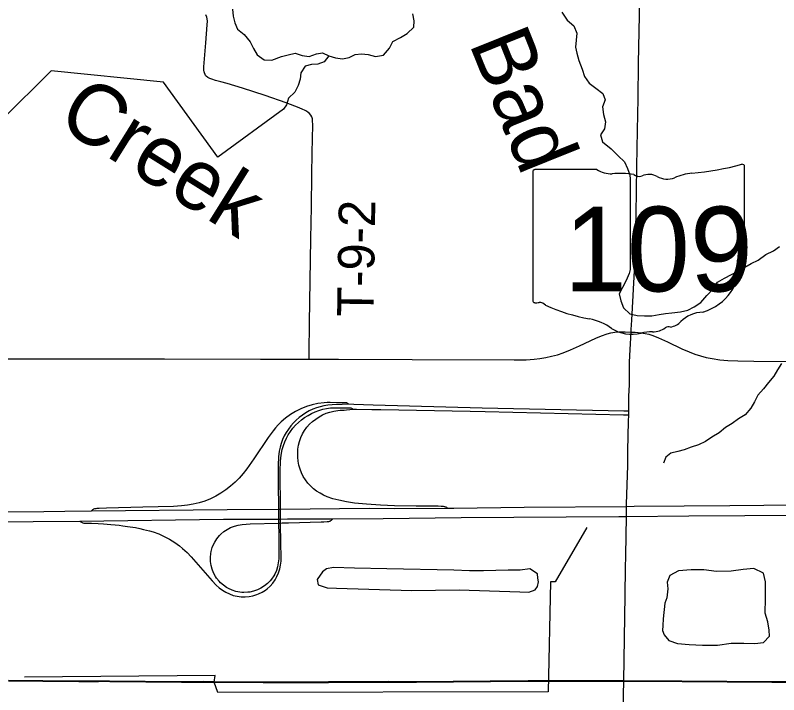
# Model space of a CAD drawing. Extents: x -21.7 to 34, y 0 to 22.
# Drawn here: x 24.718 to 25.906, y 18.47 to 19.527 of the extents above; entities that cross this region are included whole.
import ezdxf

# ---------------------------------------------------------------- set-up
doc = ezdxf.new("R2010")
doc.units = 0
for name, color, linetype in [('GM_X_County_Road', 7, 'Continuous'), ('GM_X_Interchange_Ramps', 7, 'Continuous'), ('GM_X_Interstate_Route', 7, 'Continuous'), ('GM_X_Minor_Lake', 7, 'Continuous'), ('GM_X_Minor_River', 7, 'Continuous'), ('GM_X_Minor_River_Text', 7, 'Continuous'), ('GM_X_State_Location', 7, 'Continuous'), ('GM_X_State_Route', 7, 'Continuous'), ('GM_X_State_Shield', 7, 'Continuous'), ('GM_X_Township_Road', 7, 'Continuous'), ('GM_X_Township_Road_Text', 7, 'Continuous')]:
    doc.layers.add(name, color=color, linetype=linetype)

msp = doc.modelspace()

# ---------------------------------------------------------------- linework, layer by layer
at = {"layer": 'GM_X_County_Road'}
for points in [[(24.6684, 18.492), (24.7078, 18.4915), (24.7607, 18.491), (24.8167, 18.4905), (24.8475, 18.4904), (24.8561, 18.4908), (24.8648, 18.4904), (24.9765, 18.4895), (25.0106, 18.4897), (25.0261, 18.4894), (25.1038, 18.489), (25.1753, 18.4892), (25.2057, 18.4892), (25.2989, 18.4897), (25.3424, 18.4896), (25.4575, 18.4905), (25.5165, 18.4908), (25.5538, 18.4912), (25.6651, 18.4908)], [(25.6651, 18.4908), (25.7559, 18.4905), (25.8958, 18.4896), (25.9642, 18.4893), (25.9912, 18.4891)]]:
    msp.add_lwpolyline(points, dxfattribs=at)
at = {"layer": 'GM_X_Interchange_Ramps'}
for points in [[(25.2372, 18.922), (25.2363, 18.9228), (25.2355, 18.9233), (25.2345, 18.9238), (25.2338, 18.924), (25.2327, 18.9241), (25.2318, 18.9241), (25.2297, 18.924), (25.2267, 18.9242), (25.2082, 18.9246), (25.2035, 18.9247), (25.1985, 18.9243), (25.189, 18.9232), (25.1801, 18.9212), (25.1713, 18.9183), (25.1626, 18.9147), (25.1543, 18.9106), (25.1463, 18.9061), (25.1387, 18.9005), (25.132, 18.8948), (25.1272, 18.8901), (25.1228, 18.8852), (25.1192, 18.8804), (25.1118, 18.8703), (25.0893, 18.8368), (25.0785, 18.8216), (25.0727, 18.8143), (25.0666, 18.8072), (25.0601, 18.8006), (25.0531, 18.7944), (25.0458, 18.7887), (25.038, 18.7835), (25.03, 18.7788), (25.0216, 18.7747), (25.0129, 18.7713), (25.004, 18.7685), (24.995, 18.7664), (24.9858, 18.7649), (24.9765, 18.7638), (24.9641, 18.763), (24.9166, 18.762), (24.86, 18.7601), (24.8483, 18.7598), (24.8466, 18.7598), (24.8449, 18.7596), (24.8431, 18.7594), (24.8413, 18.759), (24.8397, 18.7585), (24.8389, 18.7581), (24.838, 18.7575), (24.8371, 18.7568), (24.8364, 18.7559)], [(24.8182, 18.7401), (24.8188, 18.7395), (24.8197, 18.7388), (24.8207, 18.7383), (24.8228, 18.7376), (24.8243, 18.7371), (24.8257, 18.7369), (24.8366, 18.7367), (24.8466, 18.7363), (24.8552, 18.7358), (24.8665, 18.7348), (24.8735, 18.7343), (24.8797, 18.7337), (24.8852, 18.733), (24.8925, 18.732), (24.9051, 18.73), (24.9116, 18.7288), (24.9176, 18.7273), (24.9266, 18.7252), (24.9326, 18.7235), (24.9413, 18.7203), (24.9498, 18.7164), (24.958, 18.712), (24.966, 18.7071), (24.9735, 18.7016), (24.9783, 18.6977), (24.9852, 18.6914), (24.9916, 18.6847), (25.0243, 18.6472), (25.0307, 18.6405), (25.0354, 18.6363), (25.0403, 18.6326), (25.0456, 18.6293), (25.0512, 18.6267), (25.0571, 18.6246), (25.0631, 18.6232), (25.0693, 18.6224), (25.0755, 18.6223), (25.0817, 18.6228), (25.0878, 18.6239), (25.0938, 18.6257), (25.0967, 18.6268), (25.1022, 18.6295), (25.1075, 18.6328), (25.1099, 18.6347), (25.1145, 18.6389), (25.1186, 18.6436), (25.1222, 18.6487), (25.1252, 18.6541), (25.1277, 18.6598), (25.1297, 18.6657), (25.131, 18.6717), (25.1316, 18.6779), (25.1319, 18.6841), (25.1311, 18.7059), (25.1309, 18.7371), (25.1309, 18.7434), (25.1308, 18.7588), (25.1304, 18.8177), (25.1307, 18.8332), (25.1316, 18.8425), (25.1334, 18.8516), (25.1352, 18.8576), (25.1373, 18.8634), (25.14, 18.869), (25.1429, 18.8745), (25.1463, 18.8797), (25.15, 18.8846), (25.1542, 18.8893), (25.1586, 18.8936), (25.1633, 18.8976), (25.1683, 18.9013), (25.1736, 18.9047), (25.179, 18.9077), (25.1846, 18.9103), (25.1905, 18.9124), (25.1964, 18.9142), (25.2025, 18.9154), (25.2087, 18.9163), (25.2133, 18.9165), (25.2182, 18.9166), (25.2284, 18.9166), (25.2368, 18.9164), (25.2387, 18.9164), (25.2403, 18.9162), (25.2414, 18.9159), (25.2425, 18.9155), (25.2431, 18.915), (25.2437, 18.9142)], [(25.6731, 18.9114), (25.6655, 18.9113), (25.4446, 18.916), (25.2749, 18.9208), (25.2449, 18.9218), (25.2372, 18.922), (25.2265, 18.9216), (25.2177, 18.9214), (25.211, 18.9211), (25.2046, 18.9206), (25.1982, 18.9196), (25.1924, 18.9182), (25.1868, 18.9166), (25.181, 18.9143), (25.1754, 18.9117), (25.17, 18.9086), (25.1649, 18.9052), (25.1599, 18.9014), (25.1553, 18.8973), (25.1509, 18.8929), (25.1468, 18.8882), (25.143, 18.8833), (25.1397, 18.878), (25.1367, 18.8726), (25.1341, 18.8669), (25.132, 18.8611), (25.1302, 18.8552), (25.1289, 18.8491), (25.1276, 18.8399), (25.127, 18.8275), (25.1269, 18.7995), (25.1275, 18.7588), (25.1277, 18.7434), (25.1278, 18.737), (25.128, 18.7188), (25.1283, 18.6908), (25.128, 18.6815), (25.1273, 18.6753), (25.1261, 18.6692), (25.1243, 18.6633), (25.1218, 18.6576), (25.1203, 18.6549), (25.1168, 18.6498), (25.1148, 18.6474), (25.1104, 18.643), (25.1056, 18.6392), (25.1003, 18.6359), (25.0947, 18.6331), (25.0888, 18.6311), (25.0828, 18.6297), (25.0797, 18.6293), (25.0735, 18.629), (25.0704, 18.6292), (25.0643, 18.63), (25.0612, 18.6307), (25.0553, 18.6326), (25.0496, 18.6352), (25.0469, 18.6367), (25.0418, 18.6402), (25.0371, 18.6443), (25.035, 18.6465), (25.0311, 18.6514), (25.0294, 18.654), (25.0266, 18.6595), (25.0244, 18.6653), (25.0228, 18.6713), (25.0219, 18.6775), (25.0217, 18.6837), (25.0223, 18.6899), (25.0228, 18.6929), (25.0245, 18.6989), (25.0256, 18.7018), (25.0283, 18.7074), (25.0317, 18.7126), (25.0356, 18.7175), (25.0378, 18.7197), (25.0425, 18.7238), (25.045, 18.7256), (25.0503, 18.7288), (25.0531, 18.7301), (25.0589, 18.7322), (25.0649, 18.7338), (25.071, 18.7348), (25.0834, 18.7359), (25.1277, 18.737)], [(25.3908, 18.7602), (25.3896, 18.7611), (25.3886, 18.7616), (25.3877, 18.762), (25.3868, 18.7623), (25.3859, 18.7625), (25.3846, 18.7627), (25.3829, 18.763), (25.3807, 18.7631), (25.3763, 18.7632), (25.3651, 18.7635), (25.3418, 18.7635), (25.3082, 18.7639), (25.2864, 18.7648), (25.2646, 18.7664), (25.246, 18.7683), (25.2336, 18.7701), (25.2214, 18.7726), (25.2124, 18.775), (25.2035, 18.7781), (25.1978, 18.7806), (25.1923, 18.7836), (25.187, 18.7869), (25.1821, 18.7906), (25.1775, 18.7948), (25.1733, 18.7994), (25.1695, 18.8044), (25.1662, 18.8097), (25.1634, 18.8153), (25.1612, 18.8211), (25.1594, 18.8271), (25.1583, 18.8332), (25.1576, 18.8395), (25.1575, 18.8457), (25.1579, 18.8519), (25.1589, 18.8581), (25.1604, 18.8641), (25.1625, 18.87), (25.1651, 18.8757), (25.1683, 18.881), (25.172, 18.8861), (25.1761, 18.8908), (25.1807, 18.8951), (25.1855, 18.899), (25.1907, 18.9025), (25.1962, 18.9054), (25.2019, 18.9079), (25.2078, 18.9099), (25.2139, 18.9114), (25.2167, 18.912), (25.22, 18.9124), (25.2237, 18.9127), (25.2273, 18.9129), (25.2298, 18.913), (25.2337, 18.9134), (25.2437, 18.9142)], [(25.2437, 18.9142), (25.2492, 18.9142), (25.273, 18.9137), (25.2869, 18.9138), (25.4261, 18.9113)], [(25.4261, 18.9113), (25.4492, 18.9109), (25.665, 18.9055), (25.6729, 18.9053)], [(25.1278, 18.737), (25.1309, 18.7371), (25.1331, 18.7372), (25.1424, 18.7375), (25.1431, 18.7375), (25.194, 18.7391), (25.1981, 18.7392), (25.2035, 18.7394), (25.2047, 18.7395), (25.2062, 18.7397), (25.207, 18.7399), (25.2081, 18.7403), (25.2091, 18.7409), (25.2099, 18.7415), (25.2109, 18.7423), (25.2121, 18.7437)], [(25.964, 18.4899), (25.8956, 18.4901), (25.7557, 18.491), (25.6649, 18.4914), (25.5536, 18.4917), (25.5163, 18.4914), (25.4572, 18.4911), (25.3422, 18.4902), (25.2987, 18.4903), (25.2055, 18.4898), (25.175, 18.4897), (25.1036, 18.4896), (25.0259, 18.49), (25.0104, 18.4903), (24.9762, 18.4901), (24.8646, 18.4909), (24.8558, 18.4913), (24.8473, 18.4909), (24.8165, 18.4911), (24.7605, 18.4915), (24.7076, 18.492)], [(24.7076, 18.492), (24.7605, 18.4915), (24.8165, 18.4911), (24.8473, 18.4909), (24.8558, 18.4913), (24.8646, 18.4909), (24.9762, 18.4901), (25.0104, 18.4903), (25.0259, 18.49), (25.1036, 18.4896), (25.175, 18.4897), (25.2055, 18.4898), (25.2987, 18.4903), (25.3422, 18.4902), (25.4572, 18.4911), (25.5163, 18.4914), (25.5536, 18.4917), (25.6649, 18.4914), (25.7557, 18.491), (25.8956, 18.4901), (25.964, 18.4899)]]:
    msp.add_lwpolyline(points, dxfattribs=at)
at = {"layer": 'GM_X_Interstate_Route'}
msp.add_line((25.1419, 18.7435), (25.2121, 18.7437), dxfattribs=at)
for points in [[(23.5167, 18.7447), (23.6117, 18.7455), (23.6583, 18.7461), (23.6647, 18.7461), (23.8076, 18.7474), (24.2957, 18.7516), (24.3952, 18.7524), (24.6719, 18.7544), (24.6727, 18.7544), (24.762, 18.7551), (24.795, 18.7556), (24.8364, 18.7559), (25.0478, 18.758), (25.1275, 18.7588), (25.1308, 18.7588), (25.2686, 18.7601), (25.3084, 18.7599), (25.3908, 18.7602)], [(25.3908, 18.7602), (25.4004, 18.7603), (25.5102, 18.7619), (25.6697, 18.7631), (25.6812, 18.7632), (25.759, 18.7638), (25.8305, 18.7644), (25.9362, 18.7654)], [(25.2121, 18.7437), (25.2908, 18.7442), (25.412, 18.7455), (25.6574, 18.7473)], [(25.6574, 18.7473), (25.6695, 18.7474), (25.7665, 18.7482), (25.8535, 18.749), (25.9375, 18.7496)], [(23.5167, 18.7298), (23.5334, 18.73), (23.6643, 18.7311), (23.6702, 18.7312), (23.7573, 18.7318), (23.9221, 18.7333), (24.006, 18.734), (24.09, 18.7346), (24.2205, 18.7354), (24.3791, 18.7368), (24.4848, 18.7376), (24.6641, 18.7391), (24.6725, 18.7391), (24.8182, 18.7401)], [(24.8182, 18.7401), (25.0418, 18.7431), (25.1277, 18.7434), (25.1309, 18.7434), (25.1419, 18.7435)]]:
    msp.add_lwpolyline(points, dxfattribs=at)
at = {"layer": 'GM_X_Minor_Lake'}
for p, q in [((25.4004, 18.6636), (25.2965, 18.6659)), ((25.7292, 18.6122), (25.7268, 18.5879))]:
    msp.add_line(p, q, dxfattribs=at)
for points in [[(25.2965, 18.6659), (25.246, 18.667), (25.2134, 18.6681), (25.2024, 18.6657), (25.1962, 18.6613), (25.1876, 18.6493), (25.1896, 18.6409), (25.2032, 18.6365), (25.218, 18.6357), (25.3351, 18.632), (25.4091, 18.6334), (25.5035, 18.6301), (25.5176, 18.6298), (25.5275, 18.633), (25.5307, 18.6383), (25.5327, 18.6454), (25.5314, 18.6515), (25.5311, 18.658), (25.5188, 18.6658), (25.5039, 18.6639), (25.4853, 18.6636), (25.447, 18.6629), (25.425, 18.663), (25.4004, 18.6636)], [(25.7268, 18.5879), (25.7258, 18.5777), (25.7256, 18.5697), (25.7281, 18.5632), (25.7355, 18.5543), (25.749, 18.5499), (25.7672, 18.5479), (25.7876, 18.5471), (25.8112, 18.5473), (25.8325, 18.5503), (25.8522, 18.5502), (25.8693, 18.5498), (25.883, 18.5514), (25.8923, 18.5611), (25.8914, 18.5702), (25.8894, 18.5832), (25.8856, 18.5969), (25.8857, 18.6197), (25.886, 18.6455), (25.8829, 18.6592), (25.8679, 18.6664), (25.8511, 18.6649), (25.8325, 18.6623), (25.8097, 18.6616), (25.7897, 18.6644), (25.7699, 18.6644), (25.7505, 18.6629), (25.7367, 18.6557), (25.7327, 18.6451), (25.7336, 18.6349), (25.7325, 18.6205), (25.7292, 18.6122)]]:
    msp.add_lwpolyline(points, dxfattribs=at)
at = {"layer": 'GM_X_Minor_River'}
for points in [[(25.056, 19.5367), (25.0568, 19.5261), (25.0596, 19.5154), (25.064, 19.5058), (25.074, 19.4972), (25.0836, 19.486), (25.0887, 19.4756), (25.0945, 19.466), (25.1053, 19.4578), (25.1174, 19.4572), (25.1324, 19.4633), (25.1427, 19.4657), (25.1537, 19.4681), (25.1643, 19.4648), (25.1756, 19.4631), (25.1867, 19.4674), (25.1963, 19.4687), (25.206, 19.4643), (25.2162, 19.461), (25.2271, 19.4593), (25.2374, 19.4617), (25.247, 19.4664), (25.2569, 19.4673), (25.2671, 19.4663), (25.2788, 19.4634), (25.291, 19.4651), (25.3004, 19.4762), (25.3056, 19.4864), (25.3175, 19.4929), (25.3279, 19.4992), (25.3383, 19.5088), (25.339, 19.5186), (25.3369, 19.5293)], [(25.5688, 19.5321), (25.5773, 19.5198), (25.5873, 19.5108), (25.5923, 19.4993), (25.5909, 19.4887), (25.5899, 19.4777), (25.592, 19.4682), (25.5955, 19.4571), (25.6005, 19.4437), (25.604, 19.4319), (25.6114, 19.4218), (25.6218, 19.414), (25.6326, 19.4058), (25.6362, 19.3958), (25.6321, 19.3849), (25.6337, 19.3731), (25.6369, 19.3617), (25.6351, 19.3507), (25.6288, 19.341), (25.632, 19.3306), (25.6454, 19.3193), (25.6565, 19.3085), (25.6665, 19.2991), (25.6708, 19.2888), (25.6744, 19.2792), (25.6754, 19.2724)], [(25.206, 19.4643), (25.1986, 19.455), (25.189, 19.451), (25.1788, 19.4509), (25.1692, 19.448), (25.1625, 19.4376), (25.1615, 19.4277), (25.1583, 19.4179), (25.1531, 19.4078), (25.1434, 19.3985), (25.1401, 19.3879), (25.1354, 19.3812)], [(25.1354, 19.3812), (25.0331, 19.3064), (24.9486, 19.423), (24.7737, 19.4409), (24.6964, 19.364), (24.6882, 19.3566), (24.6787, 19.3546), (24.6688, 19.354), (24.6593, 19.3527)], [(25.6754, 19.2724), (25.6751, 19.1319)], [(25.6751, 19.1319), (25.6738, 19.1255), (25.669, 19.1146), (25.663, 19.1037), (25.6579, 19.0936), (25.6607, 19.0829), (25.665, 19.0722), (25.6746, 19.0628), (25.6863, 19.0599), (25.6973, 19.0597), (25.7087, 19.0598), (25.7205, 19.0618), (25.7304, 19.0631), (25.7399, 19.064), (25.7536, 19.066), (25.765, 19.0684), (25.775, 19.0735), (25.7854, 19.0805), (25.7948, 19.0913), (25.8049, 19.1021), (25.8112, 19.1118), (25.822, 19.1184), (25.8327, 19.1238), (25.8435, 19.1289), (25.8539, 19.1355), (25.8635, 19.141), (25.8746, 19.1464), (25.8862, 19.1549), (25.8981, 19.1607), (25.9077, 19.1673)], [(25.911, 18.9854), (25.9044, 18.9757), (25.8988, 18.9656), (25.8906, 18.9559), (25.8828, 18.9458), (25.8742, 18.9361), (25.869, 18.9256), (25.8631, 18.9159), (25.8541, 18.9055), (25.8441, 18.8992), (25.8341, 18.8919), (25.8237, 18.8857), (25.814, 18.8775), (25.8025, 18.8706), (25.7925, 18.864), (25.7817, 18.8589), (25.7699, 18.8553), (25.7591, 18.851), (25.7492, 18.8482), (25.7385, 18.8458), (25.7307, 18.8396), (25.7272, 18.8305)], [(25.6075, 18.7302), (25.5585, 18.6456), (25.5513, 18.6458), (25.5477, 18.4743), (25.0332, 18.4732), (25.0275, 18.4893), (25.0289, 18.4999), (24.7321, 18.4974)]]:
    msp.add_lwpolyline(points, dxfattribs=at)
at = {"layer": 'GM_X_State_Route'}
for points in [[(25.6769, 19.0384), (25.6777, 19.0526), (25.6822, 19.1396), (25.6845, 19.2173), (25.6855, 19.2919), (25.6864, 19.3479), (25.6874, 19.3977), (25.6884, 19.453), (25.6916, 19.6272), (25.6923, 19.668), (25.6946, 19.7858), (25.6983, 20.0004), (25.7012, 20.1404), (25.7041, 20.2896)], [(25.6753, 19.0074), (25.6767, 19.0344), (25.6769, 19.0384)], [(25.6696, 18.7592), (25.6697, 18.7631), (25.6697, 18.7664), (25.6713, 18.8269), (25.6714, 18.8397), (25.6717, 18.8501), (25.6727, 18.8954), (25.6729, 18.9053), (25.6731, 18.9114), (25.673, 18.9135), (25.6733, 18.9348), (25.6739, 18.9524), (25.6743, 18.9874), (25.6753, 19.0074)], [(25.6651, 18.4908), (25.6674, 18.6249), (25.6681, 18.6669), (25.6686, 18.6866), (25.6695, 18.7474), (25.6696, 18.7592)], [(25.661, 18.2416), (25.6623, 18.3238), (25.6644, 18.4479), (25.6651, 18.4908)]]:
    msp.add_lwpolyline(points, dxfattribs=at)
at = {"layer": 'GM_X_State_Shield'}
for p, q in [((25.5236, 19.2836), (25.5236, 19.0835)), ((25.6234, 19.2871), (25.5269, 19.2871)), ((25.8532, 19.1873), (25.8532, 19.292)), ((25.8532, 19.1874), (25.8532, 19.1873))]:
    msp.add_line(p, q, dxfattribs=at)
for centre, major_axis, start_param, end_param in [((25.7358, 19.5599), (0.3495, 0), 4.814394, 5.042369), ((25.8496, 19.2925), (0.00367, 0), 6.141152, 7.989035), ((25.5274, 19.284), (0.00382, 0), 1.712693, 3.28349), ((25.6464, 19.3103), (0.037, 0), 4.042523, 4.731795), ((25.6587, 19.1747), (0.133, 0), 1.404758, 1.657858), ((25.7804, 19.2259), (0.0703, 0), 1.699011, 2.107814), ((25.6889, 19.2851), (0.0107, 0), 3.836095, 5.185415), ((25.7045, 19.2619), (0.0222, 0), 0.950623, 2.079405), ((25.7332, 19.2937), (0.0267, 0), 4.081561, 5.145723), ((25.8493, 19.1869), (0.00393, 0), 5.05454, 6.418171), ((25.8524, 19.1796), (0.00568, 0), 1.883978, 3.671073), ((25.8162, 19.1664), (0.0341, 0), 5.934695, 6.695948), ((25.8664, 19.1435), (0.0248, 0), 2.387724, 3.262537), ((25.7554, 19.1302), (0.0874, 0), 5.101752, 6.440018), ((25.5274, 19.0831), (0.00385, 0), 3.00124, 4.508301), ((25.528, 19.1035), (0.0294, 0), 4.665946, 4.897461), ((25.534, 19.0719), (0.0106, 0), 0.519207, 1.627899), ((25.6679, 19.2517), (0.2524, 0), 4.195997, 4.488961), ((25.7923, 19.0273), (0.0479, 0), 1.647645, 2.488434), ((25.5926, 18.9936), (0.079, 0), 0.823519, 1.323587), ((25.7316, 19.0641), (0.0282, 0), 4.937069, 5.64225), ((25.678, 19.071), (0.0501, 0), 4.026481, 4.996735), ((25.707, 19.0018), (0.0412, 0), 1.495662, 1.94098), ((25.7106, 19.056), (0.0267, 0), 4.691044, 5.507374), ((25.7348, 19.0366), (0.00752, 0), 1.147584, 2.315152)]:
    msp.add_ellipse(centre, major_axis=major_axis, ratio=0.8, start_param=start_param, end_param=end_param, dxfattribs=at)
at = {"layer": 'GM_X_Township_Road'}
for points in [[(25.1753, 18.992), (25.1754, 19.0022), (25.176, 19.0489), (25.1779, 19.1796), (25.179, 19.2294), (25.1797, 19.2792), (25.1803, 19.3134), (25.181, 19.3569), (25.1808, 19.3632), (25.1804, 19.3663), (25.1796, 19.3692), (25.178, 19.3719), (25.1759, 19.3742), (25.1736, 19.3762), (25.171, 19.378), (25.1683, 19.3795), (25.1656, 19.3809), (25.1598, 19.3834), (25.1394, 19.3909), (25.1071, 19.4023), (25.0716, 19.4141), (25.0478, 19.4212), (25.0378, 19.4239), (25.0296, 19.4258), (25.0237, 19.4277), (25.0209, 19.4291), (25.0178, 19.4305), (25.0152, 19.4327), (25.0142, 19.4338), (25.0132, 19.4351), (25.0122, 19.4379), (25.0119, 19.4391), (25.0114, 19.4421), (25.0113, 19.4439), (25.0115, 19.447), (25.013, 19.4656), (25.0143, 19.4842), (25.0165, 19.5122), (25.0169, 19.5182), (25.0167, 19.5217), (25.016, 19.5246), (25.0144, 19.5279)], [(25.1753, 18.992), (25.2208, 18.9919), (25.3359, 18.9916), (25.4945, 18.9909), (25.5131, 18.9912), (25.5255, 18.9921), (25.5347, 18.9931), (25.5438, 18.9946), (25.5529, 18.9966), (25.5618, 18.9991), (25.5706, 19.002), (25.5822, 19.0065), (25.5964, 19.0128), (25.6217, 19.0248), (25.6303, 19.0284), (25.6392, 19.0315), (25.6453, 19.0331), (25.6515, 19.0342), (25.6578, 19.0347), (25.6672, 19.0348), (25.6767, 19.0344)], [(25.6767, 19.0344), (25.6828, 19.0341), (25.6921, 19.0333), (25.6983, 19.0323), (25.7044, 19.0308), (25.7104, 19.0289), (25.7191, 19.0255), (25.7333, 19.0189), (25.7557, 19.0082), (25.7671, 19.0033), (25.7758, 19), (25.7846, 18.9972), (25.7936, 18.9949), (25.8027, 18.993), (25.8149, 18.9912), (25.8273, 18.9901), (25.8428, 18.9893), (25.8676, 18.9888), (25.9207, 18.9884)], [(24.6768, 18.9929), (24.6859, 18.9928), (24.7543, 18.9927), (24.8507, 18.9925), (24.9502, 18.9927), (25.0995, 18.9922), (25.1753, 18.992)]]:
    msp.add_lwpolyline(points, dxfattribs=at)

# ---------------------------------------------------------------- texts
at = {"layer": 'GM_X_Minor_River_Text'}
for s, rotation, p in [('Bad', 291.8909, (25.4237, 19.484)), ('Creek', 328.0165, (24.7795, 19.3575))]:
    msp.add_text(s, height=0.09476, rotation=rotation, dxfattribs=at).set_placement(p)
at = {"layer": 'GM_X_State_Location'}
for s in ['s', 'r']:
    msp.add_text(s, height=0.000189, dxfattribs=at).set_placement((25.6847, 19.1703))
msp.add_text('109', height=0.000189, rotation=0, dxfattribs=at).set_placement((25.6179, 19.1565))
at = {"layer": 'GM_X_State_Shield'}
msp.add_text('109', height=0.13184, dxfattribs=at).set_placement((25.5721, 19.0976))
at = {"layer": 'GM_X_Township_Road_Text'}
msp.add_text('T-9-2', height=0.05682, rotation=89.0959, dxfattribs=at).set_placement((25.2756, 19.058))

doc.saveas('drawing.dxf')
